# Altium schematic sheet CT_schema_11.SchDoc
size 147 x 119 mm
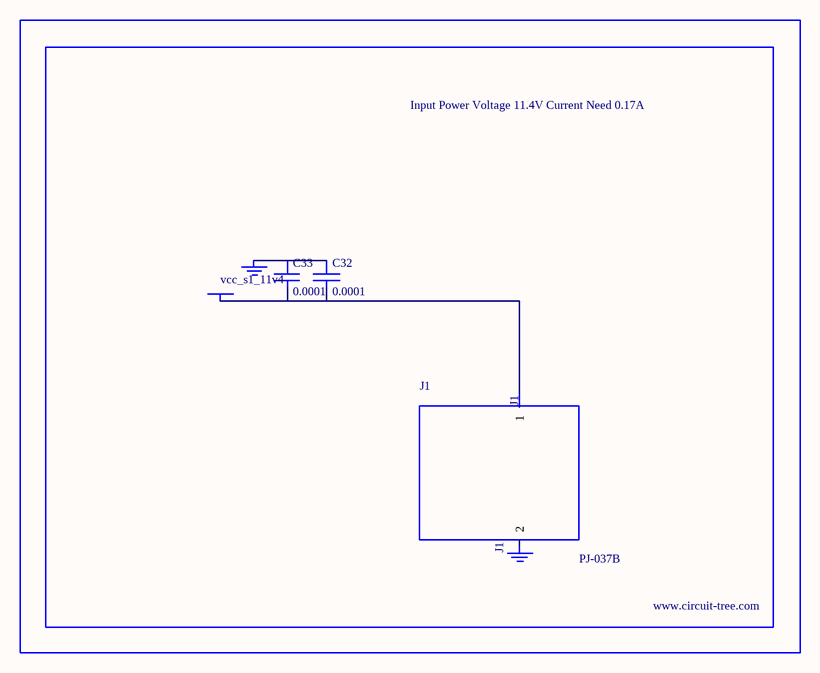
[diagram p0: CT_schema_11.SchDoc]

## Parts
BORDER10  (no value)
C32  0.0001  [EXV-9H]
C33  0.0001  [EXV-9H]
GND_INSTANCE_10_0  (no value)
GND_INSTANCE_10_1  (no value)
J1  PJ-037B  [PJ-037B_PACKAGE]
POWER_INSTANCE_10_0  vcc_s1_11v4

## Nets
NetC32_1: C32.1 C33.1 GND_INSTANCE_10_0.0(GND)
NetC32_2: C32.2 C33.2 J1.1 POWER_INSTANCE_10_0.0(PWR)

Not connected (* = marked no-connect by the designer): GND_INSTANCE_10_1 0(GND); J1 2

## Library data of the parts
BORDER10 = BORDER_PAGE10
C32 C33 = EDK107M035A9HAA
GND_INSTANCE_10_0 GND_INSTANCE_10_1 = GND
POWER_INSTANCE_10_0 = PWR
